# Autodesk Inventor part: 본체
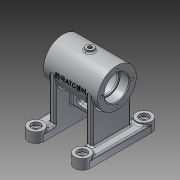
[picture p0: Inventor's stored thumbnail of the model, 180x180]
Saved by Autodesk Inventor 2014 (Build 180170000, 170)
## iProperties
Created: 2015-11
Part Number: 본체
Material: 알루미늄 6061
Document SubType Name: Modeling
Designer: USER
Density: 2.71 g/cm^3
Appearance: 알루미늄 - 평지
Mass: 358.728 g
Surface Area: 458.906 cm^2
Volume: 132.372 cm^3
Author: USER
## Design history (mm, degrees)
sketch "스케치1"
  geometry: C1 r 25 at (0, 0); 1 further point
  constraints: 1 centre point, 1 coincident
  dimensions: "d0" = 50 diameter of C1
extrude "돌출1" new body sketch "스케치1" stored distance "d1" = 70; taper "d2" = 0 deg
sketch "스케치2"
  geometry: L1 (-28, 25)-(-20, 25); L2 (-20, 25)-(-20, -25); L3 (-20, -25)-(-28, -25); L4 (-28, -25)-(-28, 25); L5 (-35, -25)-(-35, 25) reference; L6 (-35, 25)-(35, 25) reference; L7 (35, 25)-(35, -25) reference; L8 (35, -25)-(-35, -25) reference; L9 (0, 0)-(0, -10); L10 (28, -25)-(28, 25); L11 (28, 25)-(20, 25); L12 (20, 25)-(20, -25); L13 (20, -25)-(28, -25); 1 further point
  constraints: 18 end point, 4 symmetric about line, 2 parallel, 2 perpendicular, 1 horizontal, 1 horizontal alignment, 1 midpoint
  dimensions: "d3" = 20 distance from line of L9.start L2; "d4" = 8 distance between parallel lines of L2 L4; "d5" = 50 distance of L1.end L2.end
extrude "돌출2" join sketch "스케치2" distance "d6" = 68; taper "d7" = 0 deg
sketch "스케치3"
  geometry: L1 (-20, 4)-(20, 4); L2 (20, 4)-(20, -4); L3 (20, -4)-(-20, -4); L4 (-20, -4)-(-20, 4); 3 further points
  constraints: 8 end point, 2 midpoint, 2 parallel, 1 horizontal, 1 horizontal alignment, 1 perpendicular, 1 vertical alignment
  dimensions: "d8" = 8 distance of L1.end L2.end; "d9" = 40 distance of L1.start L1.end
extrude "돌출3" join sketch "스케치3" distance "d10" = 45; taper "d11" = 0 deg
sketch "스케치4"
  geometry: L1 (28, 25)-(20, 25) reference; L2 (-40, 40)-(-20, 40); L3 (-20, 40)-(-20, -40); L4 (-20, -40)-(-40, -40); L5 (-40, -40)-(-40, 40); L6 (0, 0)-(0, 36.88); L7 (28, 25)-(28, -25) reference; L8 (28, -25)-(20, -25) reference; L9 (20, -25)-(20, 25) reference; L10 (20, 25)-(28, 25) reference; L11 (-28, -25)-(-28, 25) reference; L12 (-28, 25)-(-20, 25) reference; L13 (-20, 25)-(-20, -25) reference; L14 (-20, -25)-(-28, -25) reference; L15 (28, -25)-(28, 25); L16 (28, 25)-(20, 25); L17 (40, 40)-(20, 40); L18 (40, -40)-(40, 40); L19 (20, 40)-(20, -40); L20 (20, 25)-(20, -25); L21 (20, -25)-(28, -25); L22 (20, -40)-(40, -40); 8 further points
  constraints: 26 end point, 8 symmetric about line, 5 horizontal alignment, 4 midpoint, 3 parallel, 2 vertical, 1 horizontal, 1 perpendicular, 1 vertical alignment, 8 other
  dimensions: "d12" = 80 distance of L4.end L2.start; "d13" = 20 distance of L2.start L2.end
extrude "돌출4" join sketch "스케치4" distance "d14" = 10; taper "d15" = 0 deg
sketch "스케치5"
  geometry: L1 (28, -25)-(20, -25) reference; L2 (20, -40)-(20, -25) reference; L3 (40, 40)-(40, -40) reference; L4 (20, 25)-(20, 40) reference; L5 (20, -25)-(20, 25) reference; L6 (28, 25)-(28, -25) reference; L7 (20, 25)-(28, 25) reference; L8 (-28, -25)-(-28, 25) reference; L9 (-28, 25)-(-20, 25) reference; L10 (-20, 25)-(-20, -25) reference; L11 (-20, -25)-(-20, -40) reference; L12 (-40, -40)-(-40, 40) reference; L13 (-20, 40)-(-20, 25) reference; L14 (-20, -25)-(-28, -25) reference; C1 r 10 at (-30, 40); C2 r 10 at (30, 40); C3 r 10 at (30, -40); C4 r 10 at (-30, -40); A1 r 10 centre (30, -40) between (20, -40) and (40, -40) reference; A2 r 10 centre (30, 40) between (40, 40) and (20, 40) reference; A3 r 10 centre (-30, -40) between (-40, -40) and (-20, -40) reference; A4 r 10 centre (-30, 40) between (-20, 40) and (-40, 40) reference; 1 further point
  constraints: 4 centre point, 4 coincident, 2 concentric
  dimensions: "d16" = 20 diameter of C3; "d17" = 20 diameter of C2
extrude "돌출5" join sketch "스케치5" distance "d18" = 3; taper "d19" = 0 deg
sketch "스케치6"
  geometry: L1 (0, 0)-(40, 0) reference; L2 (12, -10.322)-(28, -10.322); L3 (12, -13.822)-(28, -13.822); L4 (28, -6.822)-(12, -6.822); L5 (-15, 0)-(-15, 49.356) reference; L6 (-15, 49.356)-(55, 49.356) reference; L7 (55, 49.356)-(55, 0) reference; L8 (55, 0)-(48, 0) reference; L9 (48, 0)-(48, -33.322) reference; L10 (48, -33.322)-(60, -33.322) reference; L11 (60, -33.322)-(60, -43.322) reference; L12 (60, -43.322)-(40, -43.322) reference; L13 (40, -43.322)-(40, -20.322) reference; L14 (40, -20.322)-(0, -20.322) reference; L15 (0, 0)-(0, -20.322) reference; L16 (40, 0)-(0, 0) reference; L17 (40, -20.322)-(40, 0) reference; L18 (-8, 0)-(-15, 0) reference; L19 (-8, -33.322)-(-8, 0) reference; L20 (-20, -33.322)-(-8, -33.322) reference; L21 (-20, -43.322)-(-20, -33.322) reference; L22 (0, -43.322)-(-20, -43.322) reference; L23 (0, -20.322)-(0, -43.322) reference; A1 r 3.5 centre (12, -10.322) between (12, -6.822) and (12, -13.822); A2 r 3.5 centre (28, -10.322) between (28, -13.822) and (28, -6.822); 3 further points
  constraints: 8 end point, 4 point on circle, 4 tangent, 2 centre point, 2 midpoint, 2 parallel, 1 vertical alignment
  dimensions: "d20" = 7 distance between parallel lines of L3 L4; "d21" = 16 distance of L2.end L2.start; "d22" = 33 distance from line of L22 point (20, -10.322)
extrude "돌출6" cut sketch "스케치6" distance "d23" = 8; taper "d24" = 0 deg
sketch "스케치7"
  geometry: C1 r 21 at (0, 0); 1 further point
  constraints: 1 centre point, 1 coincident
  dimensions: "d25" = 42 diameter of C1
extrude "돌출7" cut sketch "스케치7" stored distance "d26" = 42; taper "d27" = 0 deg
sketch "스케치8"
  geometry: C1 r 14 at (0, 0); 1 further point
  constraints: 1 centre point, 1 coincident
  dimensions: "d28" = 28 diameter of C1
extrude "돌출8" cut sketch "스케치8" stored distance "d29" = 46; taper "d30" = 0 deg
sketch "스케치9"
  geometry: L1 (0, 0)-(14, -24.249); L2 (0, -21)-(0, 0); L3 (11.403, -19.751)-(6.207, -22.751); L4 (6.207, -22.751)-(8.804, -27.249); L5 (8.804, -27.249)-(14, -24.249); L6 (14, -24.249)-(11.403, -19.751)
  constraints: 12 end point, 3 perpendicular, 1 point on line, 1 vertical
  dimensions: "d31" = 30 deg angle of L1 L2; "d32" = 28 distance of L1.start L1.end; "d34" = 12 diameter of L4 L1; "d35" = 5.19376 distance of L3.end L4.end
revolve "회전1" sketch "스케치9" stored, may be unused: angle "d36" = 90 deg
node "작업 평면1"
sketch "스케치10"
  geometry: C1 r 5 at (0, 0); 1 further point
  constraints: 1 centre point, 1 coincident
  dimensions: "d37" = 10 diameter of C1
extrude "돌출9" join sketch "스케치10" stored distance "d38" = 6; taper "d39" = 0 deg
sketch "스케치11"
  geometry: C1 r 25 at (0, 0) reference; C2 r 16 at (0, 0)
  constraints: 1 centre point, 1 coincident
  dimensions: "d40" = 32 diameter of C2
extrude "돌출10" cut sketch "스케치11" distance "d41" = 12; taper "d42" = 0 deg
sketch "스케치12"
  geometry: C1 r 16 at (0, 0) reference; 1 further point
  constraints: 1 horizontal alignment
  dimensions: "d43" = 20 distance of C1.centre point (-20, 0)
hole "구멍1" sketch "스케치12" at (-20, 0) diameter "d44" = 3.242; stored, may be unused: countersink angle "d48" = 90 deg, drill point angle "d50" = 118 deg; dims "d45" = 8, "d46" = 4, "d47" = 2, "d49" = 10
sketch "스케치13"
  geometry: L1 (58, -65)-(50, -65) reference; L2 (50, -65)-(50, -15) reference; L3 (50, -15)-(58, -15) reference; L4 (58, -15)-(58, -65) reference; L5 (2, -65)-(2, -15) reference; L6 (2, -15)-(10, -15) reference; L7 (10, -15)-(10, -65) reference; L8 (10, -65)-(2, -65) reference; C1 r 10 at (0, 0) reference; C2 r 10 at (0, -80) reference; C3 r 10 at (60, -80) reference; C4 r 10 at (60, 0) reference; 5 further points
  constraints: 4 coincident
hole "구멍2" sketch "스케치13" at (0, 0), (60, 0), (60, -80), (0, -80) diameter "d54" = 6; stored, may be unused: countersink angle "d58" = 90 deg, drill point angle "d60" = 118 deg; dims "d55" = 8, "d56" = 12, "d57" = 4, "d59" = 10
sketch "스케치14"
  geometry: C1 r 5 at (0, 0) reference; 1 further point
  constraints: 1 coincident
hole "구멍3" sketch "스케치14" at (0, 0) diameter "d61" = 5.188; stored, may be unused: countersink angle "d65" = 90 deg, drill point angle "d67" = 118 deg; dims "d62" = 10, "d63" = 12, "d64" = 4, "d66" = 10
sketch "스케치15"
  geometry: C1 r 6 at (0, 0) reference; 1 further point
  constraints: 1 coincident
hole "구멍4" sketch "스케치15" at (0, 0) diameter "d68" = 5.188; stored, may be unused: countersink angle "d72" = 90 deg, drill point angle "d74" = 118 deg; dims "d69" = 10, "d70" = 12, "d71" = 4, "d73" = 10
fillet "모깎기1" dims "d75" = 0.3
fillet "모깎기2" dims "d76" = 0.3
sketch "스케치16"
  geometry: L1 (0, -58)-(8, -58) reference; L2 (8, -58)-(20, -58) reference; L3 (20, -58)-(20, -68) reference; L4 (20, -68)-(0, -68) reference; L5 (0, -68)-(0, -58) reference; L6 (0, -58)-(0, 0) reference; L7 (0, 0)-(8, 0) reference; L8 (8, 0)-(15, 0) reference; L9 (8, 0)-(8, -58) reference; L10 (-40, 0)-(0, 0) reference; L11 (-40, 0)-(-40, -58) reference; L12 (-40, -58)-(-40, -68) reference; L13 (-40, -68)-(-60, -68) reference; L14 (-60, -68)-(-60, -58) reference; L15 (-60, -58)-(-48, -58) reference; L16 (-48, -58)-(-40, -58) reference; L17 (-48, 0)-(-40, 0) reference; L18 (-48, -58)-(-48, 0) reference; L19 (-55, 0)-(-48, 0) reference; L20 (-55, 25)-(15, 25) reference; 3 further points
  constraints: 1 coincident, 1 midpoint, 1 other
  dimensions: "d79" = 25 distance from line of L20 point (-20, 0)
  node "절단 모서리 투영6"
fillet "모깎기3" dims "d77" = 2
fillet "모깎기4" dims "d78" = 2
feature "엠보싱1" dims "d8" = 8, "d9" = 40, "d80" = 0.5, "d81" = 0
fillet "모깎기5" dims "d82" = 3
fillet "모깎기6" dims "d83" = 2
fillet "모깎기7" dims "d84" = 2
chamfer "모따기1" distance "d85" = 1; stored, may be unused: second distance "d86" = 2, angle "d87" = 45 deg
fillet "모깎기8" dims "d88" = 2
node "솔리드1"
mirror "대칭1"
pattern_circular "원형 패턴1" dims angle "d52" = 360 deg
mirror "대칭2"
node "절단 모서리 투영1"
node "절단 모서리 투영2"
node "절단 모서리 투영3"
node "절단 모서리 투영4"
node "절단 모서리 투영5"
